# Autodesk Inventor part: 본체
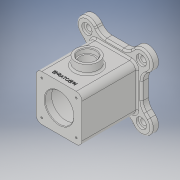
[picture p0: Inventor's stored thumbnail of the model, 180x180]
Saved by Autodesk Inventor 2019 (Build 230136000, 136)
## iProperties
Created: 2021-01
Part Number: 본체
Material: 일반
Document SubType Name: Modeling
Designer: 3DPRO3
Density: 1 g/cm^3
Appearance: 기본값
Mass: 385.404 g
Surface Area: 853.764 cm^2
Volume: 385.404 cm^3
Author: 3DPRO3
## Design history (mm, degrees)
sketch "스케치1"
  geometry: L1 (-40, 40)-(40, 40); L2 (40, 40)-(40, -40); L3 (40, -40)-(-40, -40); L4 (-40, -40)-(-40, 40); L5 (-40, 40)-(40, -40); L6 (40, 40)-(-40, -40); 1 further point
  constraints: 12 end point, 2 midpoint, 2 parallel, 1 horizontal, 1 perpendicular
  dimensions: "d0" = 80 distance of L2.end L3.end; "d1" = 80 distance of L1.end L2.end
extrude "돌출1" new body sketch "스케치1" stored distance "d2" = 108; taper "d3" = 0 deg
sketch "스케치2" dims "d6" = 134
  geometry: L1 (-48, 48)-(-48, -48); L2 (-48, -48)-(48, -48); L3 (-48, 48)-(48, -48); L4 (48, -48)-(48, 22.544); L5 (25.229, 48)-(-48, 48); L6 (60.104, 34.648)-(48, 22.544); L7 (33.054, 58.279)-(25.229, 48); L8 (0, 0)-(47.376, 47.376); L9 (0, 0)-(67, 0); A1 r 18 centre (47.376, 47.376) between (60.104, 34.648) and (33.054, 58.279); 1 further point
  constraints: 18 end point, 3 parallel, 2 coincident, 2 horizontal, 2 point on circle, 2 tangent, 1 centre point, 1 equal length, 1 midpoint, 1 perpendicular, 3 other
  dimensions: "d4" = 96 distance of L2.end L1.end; "d5" = 96 distance of L1.end L1.start; "d7" = 36 diameter of A1; "d8" = 48 distance from line of L5 point (0, 0); "d89" = 67 distance of L8.start L8.end; "d90" = 45 deg angle of L9 L8
extrude "돌출2" join sketch "스케치2" distance "d9" = 12; taper "d10" = 0 deg
sketch "스케치4"
  geometry: 2 further points
  constraints: 1 coincident
hole "구멍1" sketch "스케치4" at (0, 0) diameter "d16" = 50; stored, may be unused: countersink angle "d20" = 90 deg, drill point angle "d22" = 0 deg; dims "d17" = 8, "d18" = 4, "d19" = 2, "d21" = 12
sketch "스케치5"
  geometry: 2 further points
  constraints: 1 coincident
hole "구멍2" sketch "스케치5" at (0, 0) diameter "d23" = 70; stored, may be unused: countersink angle "d27" = 90 deg, drill point angle "d29" = 0 deg; dims "d24" = 8, "d25" = 4, "d26" = 2, "d28" = 84
sketch "스케치6"
  geometry: 2 further points
  constraints: 1 coincident
hole "구멍3" sketch "스케치6" at (0, 0) diameter "d30" = 50; stored, may be unused: countersink angle "d34" = 90 deg, drill point angle "d36" = 0 deg; dims "d31" = 8, "d32" = 4, "d33" = 2, "d35" = 12
sketch "스케치7"
  geometry: L1 (0, 80)-(0, 0) reference; L2 (-108, 62.544)-(-108, -8) reference; C1 r 20 at (-49, 40); 2 further points
  constraints: 1 centre point, 1 horizontal alignment
  dimensions: "d37" = 40 diameter of C1; "d39" = 59 distance from line of L2 C1.centre
extrude "돌출3" join sketch "스케치7" distance "d40" = 15; taper "d41" = 0 deg
sketch "스케치8"
  geometry: C1 r 20 at (0, 0) reference; 2 further points
  constraints: 1 coincident
hole "구멍4" sketch "스케치8" at (0, 0) diameter "d42" = 25; stored, may be unused: countersink angle "d46" = 90 deg, drill point angle "d48" = 0 deg; dims "d43" = 8, "d44" = 30, "d45" = 8, "d47" = 12
fillet "모깎기1" dims "d56" = 10
sketch "스케치11"
  geometry: A1 r 10 centre (-30, -30) between (-40, -30) and (-30, -40) reference; A2 r 10 centre (-30, 30) between (-30, 40) and (-40, 30) reference; A3 r 10 centre (30, 30) between (40, 30) and (30, 40) reference; A4 r 10 centre (30, -30) between (30, -40) and (40, -30) reference; 5 further points
  constraints: 4 coincident
hole "구멍6" sketch "스케치11" at (-30, -30), (-30, 30), (30, 30), (30, -30) diameter "d57" = 3.242; stored, may be unused: countersink angle "d61" = 90 deg, drill point angle "d63" = 118 deg; dims "d58" = 8, "d59" = 18, "d60" = 4, "d62" = 10
sketch "스케치13"
  geometry: L1 (0, 60)-(0, 0) reference; 2 further points
  constraints: 1 horizontal alignment, 1 other
  dimensions: "d72" = 10 distance from line of L1 point (-10, 30)
feature "엠보싱1" sketch "스케치13" dims "d0" = 80, "d1" = 80, "d73" = 0.5, "d74" = 0
fillet "모깎기3" dims "d76" = 3
fillet "모깎기4" dims "d77" = 3
chamfer "모따기1" distance "d79" = 1; stored, may be unused: second distance "d80" = 2, angle "d81" = 45 deg
fillet "모깎기6" dims "d82" = 3
chamfer "모따기2" distance "d83" = 1; stored, may be unused: second distance "d84" = 2, angle "d85" = 45 deg
fillet "모깎기10" dims "d94" = 20
fillet "모깎기11" dims "d95" = 3
sketch "스케치14"
  geometry: A1 r 15 centre (47.376, 47.376) between (56.462, 35.441) and (36.77, 57.983) reference; 2 further points
  constraints: 1 coincident
hole "구멍8" sketch "스케치14" at (47.376, 47.376) diameter "d96" = 10; stored, may be unused: countersink angle "d100" = 90 deg, drill point angle "d102" = 118 deg; dims "d97" = 8, "d98" = 18, "d99" = 4, "d101" = 10
sketch "스케치15"
  geometry: C1 r 25 at (0, 0) reference; 1 further point
extrude "돌출4" cut sketch "스케치15" extent not by distance; stored distance "d106" = 15; taper "d107" = 0 deg
chamfer "모따기3" distance "d108" = 1; stored, may be unused: second distance "d109" = 2, angle "d110" = 45 deg
sketch "스케치3"
  geometry: L1 (0, 54)-(0, -54); L2 (40, 54)-(-40, 54) reference; L3 (0, 54)-(25, 54); L4 (25, 54)-(25, 42); L5 (25, 42)-(35, 42); L6 (35, 42)-(35, -42); L7 (35, -42)-(25, -42); L8 (25, -42)-(25, -54); L9 (22.544, -54)-(-22.544, -54) reference; L10 (25, -54)-(0, -54); 2 further points
  constraints: 16 end point, 3 midpoint, 3 vertical, 2 perpendicular, 2 point on line, 1 coincident, 1 horizontal
  dimensions: "d11" = 50 diameter of L4 L1; "d12" = 70 diameter of L6 L1; "d13" = 50 diameter of L8 L1; "d14" = 84 distance between parallel lines of L7 L5; "d15" = 12 distance of L7.end L8.end
node "솔리드1"
pattern_circular "원형 패턴1" dims angle "d92" = 360 deg
pattern_circular "원형 패턴2" dims angle "d104" = 360 deg
mirror "미러4"
